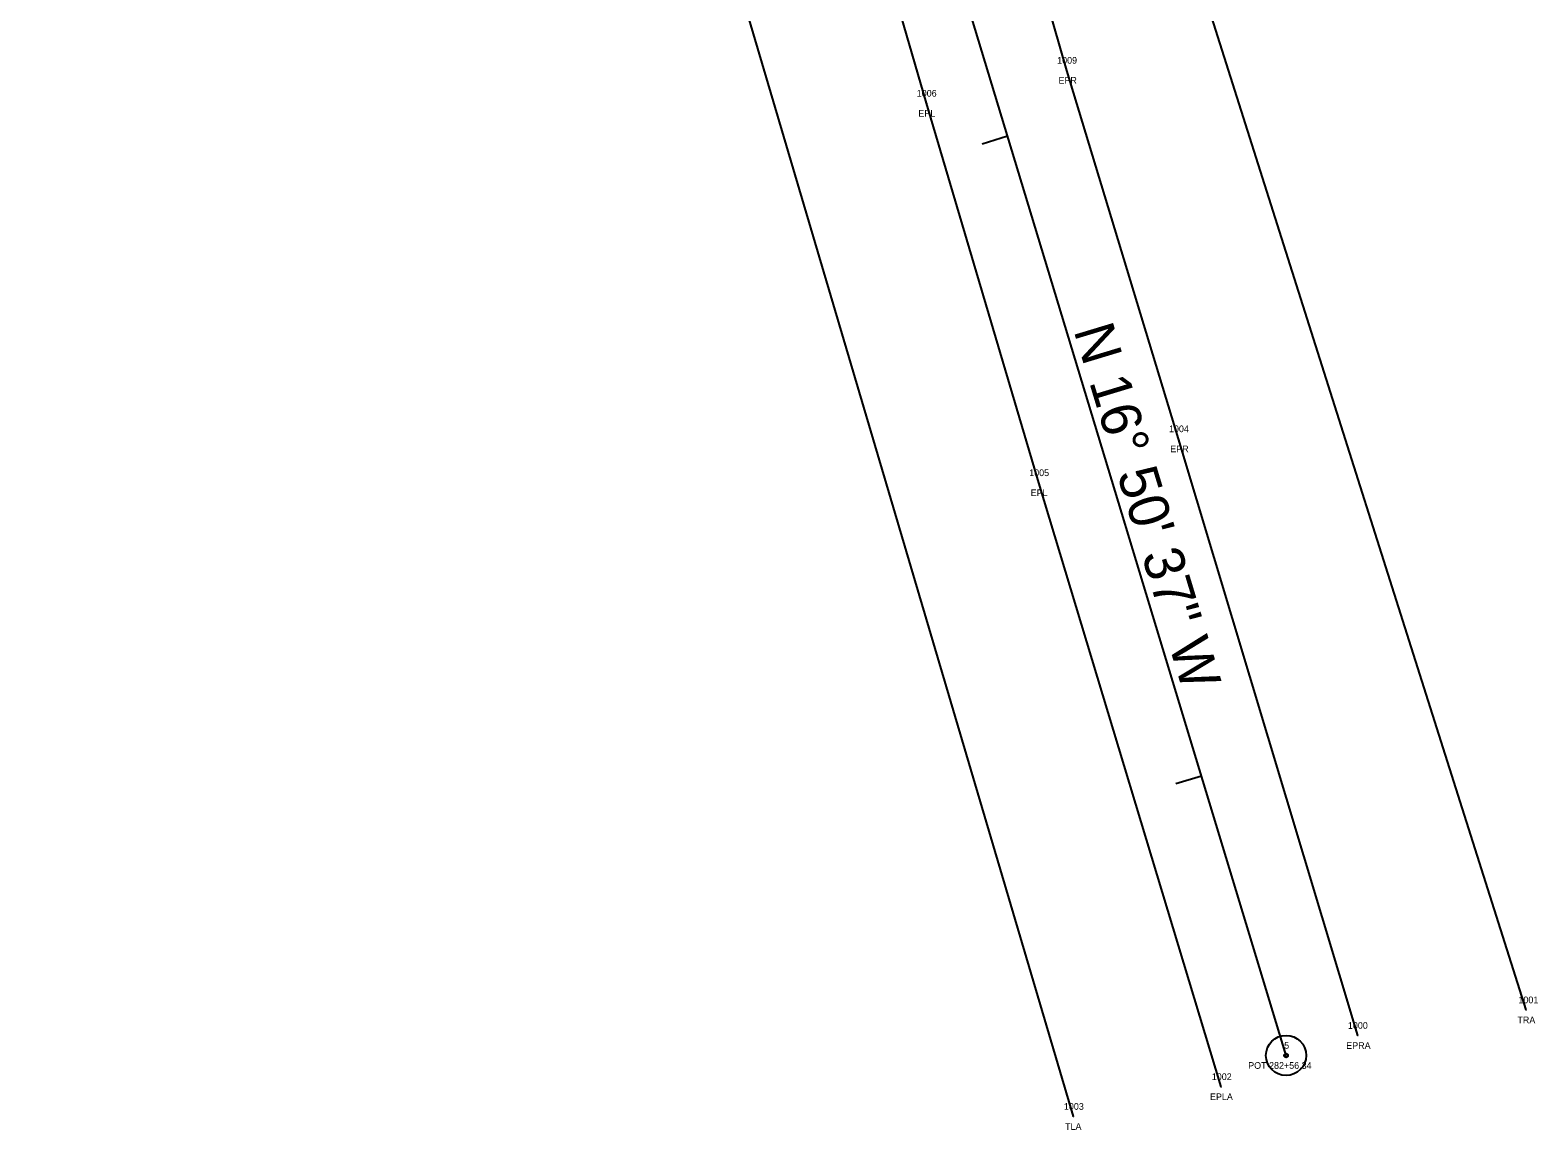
# Model space of a CAD drawing. Extents: x 2445178 to 2446205, y 790762 to 792372.
# Drawn here: x 2445672.3 to 2445897.7, y 791167.9 to 791332.4 of the extents above; entities that cross this region are included whole.
import ezdxf

# ---------------------------------------------------------------- set-up
doc = ezdxf.new("R2010")
doc.units = 0
for name, color, linetype in [('RD_EX_Road', 7, 'Continuous'), ('RD_EX_Road_txCode', 7, 'Continuous'), ('RD_EX_VEG', 7, 'Continuous'), ('RD_EX_VEG_txCode', 7, 'Continuous'), ('RD_HC_Cl', 7, 'Continuous'), ('RD_HC_Data', 7, 'Continuous'), ('RD_HC_Data_Tic', 7, 'Continuous'), ('RD_HC_txCode', 7, 'Continuous'), ('RD_SMD_Locator', 7, 'Continuous')]:
    doc.layers.add(name, color=color, linetype=linetype)

msp = doc.modelspace()

# ---------------------------------------------------------------- linework, layer by layer
at = {"layer": 'RD_EX_Road'}
for points in [[(2445850.42, 791174.36), (2445823.13, 791264.7), (2445806.34, 791321.46), (2445789.41, 791379.89), (2445773.46, 791437.57), (2445759.36, 791494.22), (2445744.01, 791559.83), (2445740.09, 791577.64), (2445731.05, 791621.01), (2445722.21, 791669.43), (2445711, 791738.26), (2445706.49, 791765.2), (2445707.32, 791765.82), (2445706.36, 791771.19), (2445705.53, 791771.38), (2445701.96, 791795.92), (2445699.57, 791813.34), (2445693.24, 791870.48), (2445688.14, 791921.92), (2445683.42, 791987.19), (2445680.88, 792033.67), (2445678.74, 792090.55), (2445675.91, 792199.23), (2445673.61, 792301.11)], [(2445870.82, 791182.02), (2445844.02, 791271.27), (2445827.31, 791326.39), (2445810.32, 791385.52), (2445794.94, 791441.92), (2445780.98, 791497.5), (2445766.72, 791558.1)]]:
    msp.add_lwpolyline(points, dxfattribs=at)
at = {"layer": 'RD_EX_VEG'}
for points in [[(2445895.98, 791185.85), (2445831.19, 791390.71), (2445805.05, 791501.58), (2445775.97, 791631.01), (2445748.83, 791769.92)], [(2445828.32, 791169.91), (2445768.75, 791371.54), (2445736.16, 791487.68), (2445726.82, 791546.26), (2445672.34, 791533.07)]]:
    msp.add_lwpolyline(points, dxfattribs=at)
at = {"layer": 'RD_HC_Cl'}
msp.add_line((2445860.1, 791179.04), (2445811.6, 791339.27), dxfattribs=at)
at = {"layer": 'RD_HC_Data'}
for radius in [3, 0.282]:
    msp.add_circle((2445860.1, 791179.04), radius, dxfattribs=at)
at = {"layer": 'RD_HC_Data_Tic'}
for p, q in [((2445818.48, 791316.53), (2445814.65, 791315.37)), ((2445847.45, 791220.82), (2445843.63, 791219.66))]:
    msp.add_line(p, q, dxfattribs=at)
at = {"layer": 'RD_SMD_Locator'}
for centre in [(2445827.31, 791326.39), (2445806.34, 791321.46), (2445844.02, 791271.27), (2445823.13, 791264.7), (2445895.98, 791185.85), (2445870.82, 791182.02), (2445860.1, 791179.04), (2445850.42, 791174.36), (2445828.32, 791169.91)]:
    msp.add_circle(centre, 0.001, dxfattribs=at)

# ---------------------------------------------------------------- texts
at = {"layer": 'RD_EX_Road_txCode'}
for s, p in [('1009', (2445825.88, 791327.39)), ('EPR', (2445826.08, 791324.39)), ('1006', (2445804.89, 791322.46)), ('EPL', (2445805.13, 791319.46)), ('1004', (2445842.6, 791272.27)), ('EPR', (2445842.79, 791269.27)), ('1005', (2445821.7, 791265.7)), ('EPL', (2445821.92, 791262.7)), ('1000', (2445869.35, 791183.02)), ('EPRA', (2445869.1, 791180.02)), ('1002', (2445849, 791175.36)), ('EPLA', (2445848.73, 791172.36))]:
    msp.add_text(s, height=1, dxfattribs=at).set_placement(p)
at = {"layer": 'RD_EX_VEG_txCode'}
for s, p in [('1001', (2445894.84, 791186.85)), ('TRA', (2445894.69, 791183.85)), ('1003', (2445826.89, 791170.91)), ('TLA', (2445827.06, 791167.91))]:
    msp.add_text(s, height=1, dxfattribs=at).set_placement(p)
at = {"layer": 'RD_HC_Data'}
msp.add_text('N 16%%d 50\' 37" W', height=6, rotation=286.8436, dxfattribs=at).set_placement((2445828.31, 791287.5))
at = {"layer": 'RD_HC_txCode'}
for s, p in [('5', (2445859.82, 791180.04)), ('POT 282+56.34', (2445854.44, 791177.04))]:
    msp.add_text(s, height=1, dxfattribs=at).set_placement(p)

doc.saveas('drawing.dxf')
